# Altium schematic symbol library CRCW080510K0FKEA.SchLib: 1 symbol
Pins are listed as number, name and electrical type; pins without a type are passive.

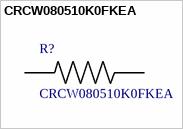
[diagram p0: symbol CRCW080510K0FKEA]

## CRCW080510K0FKEA
designator R?
10 kOhms Â±1% 0.125W, 1/8W Chip Resistor 0805 _2012 Metric_ Automotive AEC-Q200 Thick Film; MF: Vishay
footprint *RESC2012X50N
pins: 1, 2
